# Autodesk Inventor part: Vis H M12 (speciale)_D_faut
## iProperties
Created: 2011-10
Part Number: Vis H M12 (speciale)_D_faut
Document SubType Name: Modeling
Designer: Bruno
Author: Bruno
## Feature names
1. Base1
